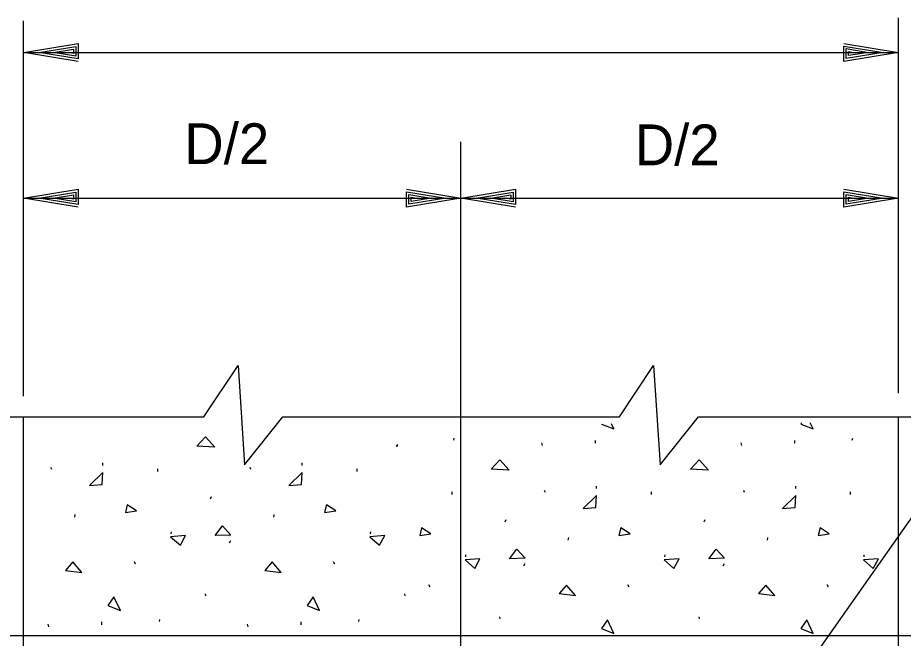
# Model space of a CAD drawing. Extents: x 44743.44 to 44747.1, y 44738.46 to 44741.29.
# Drawn here: x 44744.2286 to 44744.4817, y 44739.7624 to 44739.9399 of the extents above; entities that cross this region are included whole.
import ezdxf

# ---------------------------------------------------------------- set-up
doc = ezdxf.new("R2010")
doc.units = 0
for name, color, linetype in [('Level 1', 7, 'Continuous'), ('Level 10', 7, 'Continuous'), ('Level 2', 7, 'Continuous'), ('Level 8', 7, 'Continuous'), ('S-ANNO-TEXT', 7, 'Continuous')]:
    doc.layers.add(name, color=color, linetype=linetype)

msp = doc.modelspace()

# ---------------------------------------------------------------- linework, layer by layer
at = {"layer": 'Level 1'}
for p, q in [((44744.23024, 44739.83163), (44744.23024, 44739.93897)), ((44744.48024, 44739.83254), (44744.48024, 44739.93988)), ((44744.23024, 44739.92994), (44744.48024, 44739.92994)), ((44744.23024, 44739.92994), (44744.23024, 44739.92994)), ((44744.23458, 44739.92994), (44744.23458, 44739.92994)), ((44744.47591, 44739.92994), (44744.47591, 44739.92994)), ((44744.48024, 44739.92994), (44744.48024, 44739.92994)), ((44744.35524, 44739.48171), (44744.35524, 44739.90439)), ((44744.43117, 44739.72177), (44744.55805, 44739.90226)), ((44744.23024, 44739.88828), (44744.35524, 44739.88828)), ((44744.23024, 44739.88828), (44744.23024, 44739.88828)), ((44744.23458, 44739.88828), (44744.23458, 44739.88828)), ((44744.35091, 44739.88828), (44744.35091, 44739.88828)), ((44744.35524, 44739.88828), (44744.48024, 44739.88828)), ((44744.35524, 44739.88828), (44744.35524, 44739.88828)), ((44744.35524, 44739.88828), (44744.35524, 44739.88828)), ((44744.35958, 44739.88828), (44744.35958, 44739.88828)), ((44744.47591, 44739.88828), (44744.47591, 44739.88828)), ((44744.48024, 44739.88828), (44744.48024, 44739.88828)), ((44744.16371, 44739.82578), (44744.2818, 44739.82578)), ((44744.30433, 44739.82578), (44744.40056, 44739.82578)), ((44744.4231, 44739.82578), (44744.53668, 44739.82578)), ((44744.35321, 44739.81912), (44744.35332, 44739.8197)), ((44744.35272, 44739.80356), (44744.35272, 44739.80434)), ((44744.3566, 44739.78575), (44744.35665, 44739.78632))]:
    msp.add_line(p, q, dxfattribs=at)
for points in [[(44744.24583, 44739.92736), (44744.23024, 44739.92994), (44744.24583, 44739.93253), (44744.24583, 44739.92811), (44744.23458, 44739.92994), (44744.24516, 44739.93169), (44744.24516, 44739.92886), (44744.23874, 44739.92994), (44744.24449, 44739.93086), (44744.24449, 44739.92969), (44744.24308, 44739.92994)], [(44744.46466, 44739.93253), (44744.48024, 44739.92994), (44744.46466, 44739.92736), (44744.46466, 44739.93178), (44744.47591, 44739.92994), (44744.46533, 44739.92819), (44744.46533, 44739.93103), (44744.47174, 44739.92994), (44744.46599, 44739.92903), (44744.46599, 44739.93019), (44744.46741, 44739.92994)], [(44744.24583, 44739.88569), (44744.23024, 44739.88828), (44744.24583, 44739.89086), (44744.24583, 44739.88644), (44744.23458, 44739.88828), (44744.24516, 44739.89003), (44744.24516, 44739.88719), (44744.23874, 44739.88828), (44744.24449, 44739.88919), (44744.24449, 44739.88803), (44744.24308, 44739.88828)], [(44744.33966, 44739.89086), (44744.35524, 44739.88828), (44744.33966, 44739.88569), (44744.33966, 44739.89011), (44744.35091, 44739.88828), (44744.34033, 44739.88653), (44744.34033, 44739.88936), (44744.34674, 44739.88828), (44744.34099, 44739.88736), (44744.34099, 44739.88853), (44744.34241, 44739.88828)], [(44744.37083, 44739.88569), (44744.35524, 44739.88828), (44744.37083, 44739.89086), (44744.37083, 44739.88644), (44744.35958, 44739.88828), (44744.37016, 44739.89003), (44744.37016, 44739.88719), (44744.36374, 44739.88828), (44744.36949, 44739.88919), (44744.36949, 44739.88803), (44744.36808, 44739.88828)], [(44744.46466, 44739.89086), (44744.48024, 44739.88828), (44744.46466, 44739.88569), (44744.46466, 44739.89011), (44744.47591, 44739.88828), (44744.46533, 44739.88653), (44744.46533, 44739.88936), (44744.47174, 44739.88828), (44744.46599, 44739.88736), (44744.46599, 44739.88853), (44744.46741, 44739.88828)], [(44744.2818, 44739.82578), (44744.29155, 44739.8404), (44744.29337, 44739.81208), (44744.30433, 44739.82578)], [(44744.40056, 44739.82578), (44744.41031, 44739.8404), (44744.41213, 44739.81208), (44744.4231, 44739.82578)], [(44744.39543, 44739.82368), (44744.39542, 44739.82366)], [(44744.39542, 44739.82366), (44744.39897, 44739.82229)], [(44744.39897, 44739.82229), (44744.39825, 44739.82376)], [(44744.4526, 44739.82402), (44744.45236, 44739.82366)], [(44744.45592, 44739.82229), (44744.45506, 44739.82404)]]:
    msp.add_lwpolyline(points, dxfattribs=at)
at = {"layer": 'Level 10'}
for p, q in [((44744.23024, 44739.68828), (44744.23024, 44739.82578)), ((44744.48024, 44739.68828), (44744.48024, 44739.82578))]:
    msp.add_line(p, q, dxfattribs=at)
at = {"layer": 'Level 2'}
msp.add_line((44744.10524, 44739.76328), (44744.60524, 44739.76328), dxfattribs=at)
at = {"layer": 'Level 8'}
for p, q in [((44744.39373, 44739.81819), (44744.39373, 44739.81897)), ((44744.45067, 44739.81819), (44744.45067, 44739.81897)), ((44744.46709, 44739.81912), (44744.46719, 44739.8197)), ((44744.37858, 44739.81757), (44744.37835, 44739.81835)), ((44744.43551, 44739.81757), (44744.4353, 44739.81835)), ((44744.23829, 44739.81068), (44744.23807, 44739.81123)), ((44744.25293, 44739.81183), (44744.25293, 44739.81256)), ((44744.29522, 44739.81068), (44744.295, 44739.81123)), ((44744.30988, 44739.81183), (44744.30988, 44739.81256)), ((44744.2686, 44739.81014), (44744.2686, 44739.81092)), ((44744.32554, 44739.81014), (44744.32554, 44739.81092)), ((44744.394, 44739.80525), (44744.394, 44739.80597)), ((44744.45094, 44739.80525), (44744.45094, 44739.80597)), ((44744.37936, 44739.8041), (44744.37913, 44739.80465)), ((44744.40967, 44739.80356), (44744.40967, 44739.80434)), ((44744.4363, 44739.8041), (44744.43608, 44739.80465)), ((44744.46661, 44739.80356), (44744.46661, 44739.80434)), ((44744.28371, 44739.80233), (44744.284, 44739.80294)), ((44744.24485, 44739.79709), (44744.24496, 44739.79784)), ((44744.30179, 44739.79709), (44744.30191, 44739.79784)), ((44744.36785, 44739.79575), (44744.36813, 44739.79636)), ((44744.42479, 44739.79575), (44744.42507, 44739.79636)), ((44744.27246, 44739.79233), (44744.27251, 44739.7929)), ((44744.32941, 44739.79233), (44744.32946, 44739.7929)), ((44744.38592, 44739.79051), (44744.38604, 44739.79126)), ((44744.44286, 44739.79051), (44744.44297, 44739.79126)), ((44744.2891, 44739.78972), (44744.28948, 44739.79038)), ((44744.41354, 44739.78575), (44744.41359, 44739.78632)), ((44744.47047, 44739.78575), (44744.47052, 44739.78632)), ((44744.26227, 44739.78363), (44744.26192, 44739.78433)), ((44744.31921, 44739.78363), (44744.31886, 44739.78433)), ((44744.37322, 44739.78314), (44744.37361, 44739.7838)), ((44744.43016, 44739.78314), (44744.43056, 44739.7838)), ((44744.3464, 44739.77705), (44744.34605, 44739.77775)), ((44744.40334, 44739.77705), (44744.40298, 44739.77775)), ((44744.46027, 44739.77705), (44744.45993, 44739.77775)), ((44744.28233, 44739.77456), (44744.28227, 44739.77519)), ((44744.33926, 44739.77456), (44744.33921, 44739.77519)), ((44744.36645, 44739.76797), (44744.3664, 44739.76861)), ((44744.42339, 44739.76797), (44744.42334, 44739.76861)), ((44744.2375, 44739.7657), (44744.23729, 44739.76648)), ((44744.25266, 44739.76633), (44744.25266, 44739.76711)), ((44744.26908, 44739.76726), (44744.26918, 44739.76784)), ((44744.29444, 44739.7657), (44744.29422, 44739.76648)), ((44744.3096, 44739.76633), (44744.3096, 44739.76711)), ((44744.32602, 44739.76726), (44744.32613, 44739.76784))]:
    msp.add_line(p, q, dxfattribs=at)
for points in [[(44744.45236, 44739.82366), (44744.45592, 44739.82229)], [(44744.33671, 44739.81737), (44744.33716, 44739.81786)], [(44744.33719, 44739.81734), (44744.33671, 44739.81737)]]:
    msp.add_lwpolyline(points, dxfattribs=at)
for points in [[(44744.27977, 44739.81737), (44744.28224, 44739.82006), (44744.2849, 44739.81709)], [(44744.3639, 44739.81079), (44744.36637, 44739.81347), (44744.36902, 44739.81051)], [(44744.42084, 44739.81079), (44744.42332, 44739.81347), (44744.42597, 44739.81051)], [(44744.25274, 44739.80639), (44744.25293, 44739.80987), (44744.24908, 44739.80611)], [(44744.30968, 44739.80639), (44744.30988, 44739.80987), (44744.30602, 44739.80611)], [(44744.39381, 44739.79981), (44744.394, 44739.80329), (44744.39015, 44739.79953)], [(44744.45074, 44739.79981), (44744.45094, 44739.80329), (44744.44709, 44739.79953)], [(44744.25934, 44739.79845), (44744.2625, 44739.79886), (44744.25985, 44739.80064)], [(44744.31629, 44739.79845), (44744.31944, 44739.79886), (44744.31679, 44739.80064)], [(44744.285, 44739.79179), (44744.2871, 44739.79456), (44744.28946, 44739.79189)], [(44744.34346, 44739.79187), (44744.34663, 44739.79228), (44744.34397, 44739.79406)], [(44744.40041, 44739.79187), (44744.40358, 44739.79228), (44744.40092, 44739.79406)], [(44744.45735, 44739.79187), (44744.46051, 44739.79228), (44744.45786, 44739.79406)], [(44744.27227, 44739.79148), (44744.27505, 44739.78902), (44744.27652, 44739.79179)], [(44744.32921, 44739.79148), (44744.33198, 44739.78902), (44744.33347, 44739.79179)], [(44744.36913, 44739.7852), (44744.37123, 44739.78797), (44744.37359, 44739.78531)], [(44744.42608, 44739.7852), (44744.42817, 44739.78797), (44744.43052, 44739.78531)], [(44744.24692, 44739.78129), (44744.24434, 44739.78426), (44744.24227, 44739.7818)], [(44744.30386, 44739.78129), (44744.30129, 44739.78426), (44744.29921, 44739.7818)], [(44744.3564, 44739.7849), (44744.35917, 44739.78243), (44744.36066, 44739.7852)], [(44744.41334, 44739.7849), (44744.41611, 44739.78243), (44744.4176, 44739.7852)], [(44744.47027, 44739.7849), (44744.47306, 44739.78243), (44744.47454, 44739.7852)], [(44744.38798, 44739.7747), (44744.38541, 44739.77767), (44744.38334, 44739.77521)], [(44744.44493, 44739.7747), (44744.44235, 44739.77767), (44744.44027, 44739.77521)], [(44744.25436, 44739.7718), (44744.25791, 44739.77042), (44744.25604, 44739.77426)], [(44744.3113, 44739.7718), (44744.31485, 44739.77042), (44744.31297, 44739.77426)], [(44744.39542, 44739.76521), (44744.39897, 44739.76384), (44744.3971, 44739.76767)], [(44744.45236, 44739.76521), (44744.45592, 44739.76384), (44744.45405, 44739.76767)]]:
    msp.add_lwpolyline(points, close=True, dxfattribs=at)

# ---------------------------------------------------------------- texts
at = {"layer": 'S-ANNO-TEXT'}
for p in [(44744.27617, 44739.89801), (44744.40491, 44739.89769)]:
    msp.add_text('D/2', height=0.011667, dxfattribs=at).set_placement(p)

doc.saveas('drawing.dxf')
